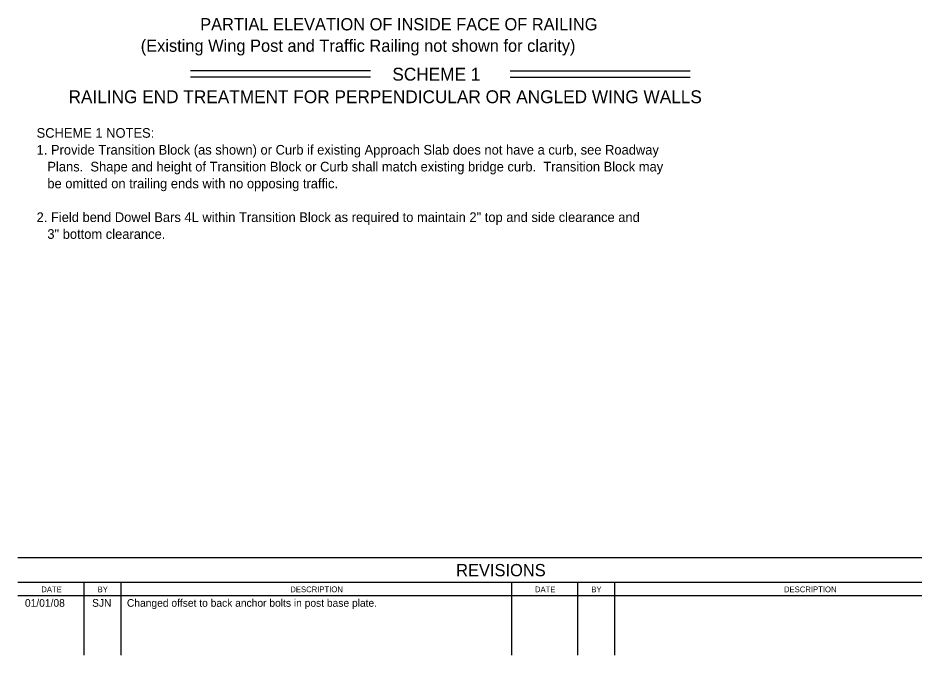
# Model space of a CAD drawing. Extents: x 21526.6 to 21598.7, y 56118.9 to 56155.9.
# Drawn here: x 21526.6 to 21545.31, y 56118.87 to 56132.18 of the extents above; entities that cross this region are included whole.
import ezdxf

# ---------------------------------------------------------------- set-up
doc = ezdxf.new("R2010")
doc.units = 0
doc.layers.add('Border', color=7, linetype='Continuous')
doc.layers.add('PlotBorder_dp', color=7, linetype='Continuous')

msp = doc.modelspace()

# ---------------------------------------------------------------- linework, layer by layer
at = {"layer": 'Border'}
for p, q in [((21547.212, 56120.898), (21526.6, 56120.898)), ((21547.212, 56120.383), (21526.6, 56120.383)), ((21527.977, 56120.383), (21527.977, 56118.868)), ((21528.751, 56120.383), (21528.751, 56118.868)), ((21536.907, 56120.383), (21536.907, 56118.868)), ((21538.283, 56120.383), (21538.283, 56118.868)), ((21539.057, 56120.383), (21539.057, 56118.868)), ((21526.6, 56120.11), (21547.212, 56120.11))]:
    msp.add_line(p, q, dxfattribs=at)
at = {"layer": 'PlotBorder_dp'}
for p, q in [((21533.962, 56131.073), (21530.203, 56131.073)), ((21536.877, 56131.073), (21540.636, 56131.073)), ((21533.962, 56130.939), (21530.203, 56130.939)), ((21536.877, 56130.939), (21540.636, 56130.939))]:
    msp.add_line(p, q, dxfattribs=at)

# ---------------------------------------------------------------- texts
at = {"layer": 'Border'}
for s, height, p in [('REVISIONS', 0.2567, (21535.749, 56120.514)), ('BY', 0.1201, (21528.265, 56120.18)), ('BY', 0.1201, (21538.571, 56120.18)), ('01/01/08', 0.16, (21526.747, 56119.877)), ('SJN', 0.16, (21528.149, 56119.877)), ('Changed offset to back anchor bolts in post base plate.', 0.16, (21528.876, 56119.877))]:
    msp.add_text(s, height=height, dxfattribs=at).set_placement(p)
for s, height, rotation, p in [('DATE', 0.1196, 359.8693, (21527.089, 56120.181)), ('DESCRIPTION', 0.12007, 0.0498, (21532.287, 56120.18)), ('DATE', 0.1196, 359.8693, (21537.395, 56120.181)), ('DESCRIPTION', 0.12007, 0.0498, (21542.593, 56120.18))]:
    msp.add_text(s, height=height, rotation=rotation, dxfattribs=at).set_placement(p)
at = {"layer": 'PlotBorder_dp'}
for s, height, p in [('PARTIAL ELEVATION OF INSIDE FACE OF RAILING', 0.256, (21530.405, 56131.917)), ('(Existing Wing Post and Traffic Railing not shown for clarity)', 0.256, (21529.164, 56131.469)), ('SCHEME 1', 0.2688, (21534.417, 56130.867)), ('RAILING END TREATMENT FOR PERPENDICULAR OR ANGLED WING WALLS', 0.2688, (21527.657, 56130.396)), ('SCHEME 1 NOTES:', 0.2016, (21526.99, 56129.674)), ('1. Provide Transition Block (as shown) or Curb if existing Approach Slab does not have a curb, see Roadway ', 0.2016, (21526.99, 56129.322)), ('   Plans.  Shape and height of Transition Block or Curb shall match existing bridge curb.  Transition Block may ', 0.2016, (21526.99, 56128.97)), ('   be omitted on trailing ends with no opposing traffic. ', 0.2016, (21526.99, 56128.618)), ('2. Field bend Dowel Bars 4L within Transition Block as required to maintain 2" top and side clearance and ', 0.2016, (21526.99, 56127.914)), ('   3" bottom clearance.', 0.2016, (21526.99, 56127.562))]:
    msp.add_text(s, height=height, dxfattribs=at).set_placement(p)

doc.saveas('drawing.dxf')
